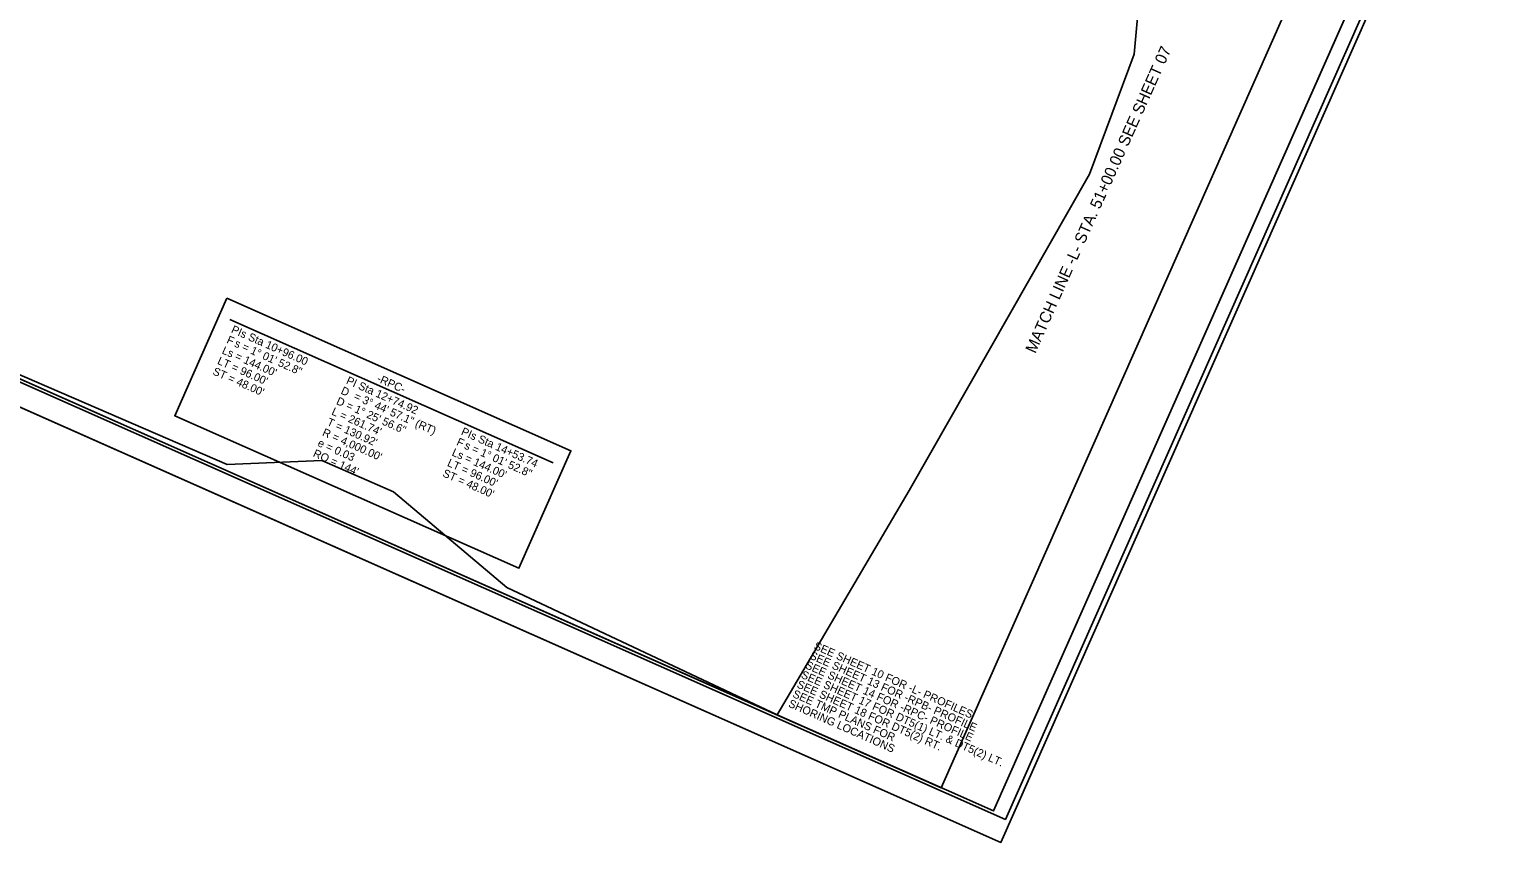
# Model space of a CAD drawing. Extents: x 1638962 to 2864602, y 841929 to 973236.
# Drawn here: x 1639652 to 1640945, y 841929 to 842639 of the extents above; entities that cross this region are included whole.
import ezdxf

# ---------------------------------------------------------------- set-up
doc = ezdxf.new("R2010")
doc.units = 0
for name, color, linetype in [('DEV STATIONARY SIGN DUAL MOUNT CELL', 7, 'Continuous'), ('Exist DTM Spot Elevation Cogo Number', 7, 'Continuous'), ('Exist Mkg Solid White Stop Bar', 7, 'Continuous'), ('Prop EOT', 7, 'Continuous'), ('Prop Mkg 3ft Min Skp 9ft White', 7, 'Continuous'), ('Prop Mkg Solid White Edge Line', 7, 'Continuous'), ('Prop Paved Shoulder', 7, 'Continuous'), ('Prop Roadway Bridge', 7, 'Continuous'), ('TCP Linework', 7, 'Continuous')]:
    doc.layers.add(name, color=color, linetype=linetype)

msp = doc.modelspace()

# ---------------------------------------------------------------- linework, layer by layer
at = {"layer": 'DEV STATIONARY SIGN DUAL MOUNT CELL'}
for points in [[(1640920.4, 842915.9), (1639549.1, 843524), (1639123.5, 842564.1), (1640494.7, 841956.1)], [(1639123.5, 842564.1), (1639549.1, 843523.9), (1640737.5, 842997), (1640676.7, 842859.8), (1640859.5, 842778.8), (1640494.7, 841956.1)]]:
    msp.add_lwpolyline(points, close=True, dxfattribs=at)
at = {"layer": 'Exist DTM Spot Elevation Cogo Number'}
msp.add_line((1639826.8, 842385.7), (1640109.4, 842260.4), dxfattribs=at)
msp.add_line((1639826.8, 842385.7), (1640109.4, 842260.4), dxfattribs=at)
msp.add_lwpolyline([(1639824.1, 842404.3), (1640125, 842270.9), (1640079.5, 842168.2), (1639778.6, 842301.6)], close=True, dxfattribs=at)
msp.add_lwpolyline([(1639824.1, 842404.3), (1640125, 842270.9), (1640079.5, 842168.2), (1639778.6, 842301.6)], close=True, dxfattribs=at)
at = {"layer": 'Prop EOT'}
msp.add_lwpolyline([(1639169.2, 842543.8), (1640449, 841976.3), (1640788.9, 842742.9), (1640615.9, 842819.6), (1640701.6, 843012.9), (1639594.8, 843503.7)], close=True, dxfattribs=at)
msp.add_lwpolyline([(1640629.1, 842742.4), (1640617.7, 842617.6), (1640578.7, 842512.8), (1640420.8, 842236.2), (1640305.4, 842040), (1640068.9, 842151.5), (1639969.8, 842235), (1639907.3, 842262.5), (1639824.3, 842259), (1639335.5, 842470.1)], dxfattribs=at)
at = {"layer": 'Prop Mkg 3ft Min Skp 9ft White'}
msp.add_line((1638962.2, 842611), (1640501.1, 841928.6), dxfattribs=at)
at = {"layer": 'Prop Mkg Solid White Edge Line'}
msp.add_line((1640578.7, 842512.8), (1640617.7, 842617.5), dxfattribs=at)
for points in [[(1640484.6, 842999.7), (1640629.1, 842742.4), (1640617.7, 842617.5)], [(1640578.7, 842512.8), (1640578.7, 842512.8), (1640420.8, 842236.2)]]:
    msp.add_lwpolyline(points, dxfattribs=at)
at = {"layer": 'Prop Paved Shoulder'}
msp.add_lwpolyline([(1638982.1, 842624), (1640505.1, 841948.7), (1640932.8, 842913.1), (1639409.8, 843588.4)], close=True, dxfattribs=at)
at = {"layer": 'Prop Roadway Bridge'}
msp.add_lwpolyline([(1638962.2, 842611), (1640501.1, 841928.6), (1640945, 842929.6), (1639406, 843612)], close=True, dxfattribs=at)
msp.add_lwpolyline([(1638962.2, 842611), (1640501.1, 841928.6), (1640945, 842929.6), (1639406, 843612)], close=True, dxfattribs=at)

# ---------------------------------------------------------------- texts
at = {"layer": 'Exist DTM Spot Elevation Cogo Number'}
for s, p in [('PIs Sta 10+96.00', (1639827.3, 842374.5)), ("Ls = 144.00'", (1639819.2, 842356.2)), ('F', (1639823.3, 842365.4)), ('s = 1%%d 01\' 52.8"', (1639830.1, 842362.3)), ("LT = 96.00'", (1639815.2, 842347.1)), ("ST = 48.00'", (1639811.1, 842337.9)), ('PI Sta 12+74.92', (1639927.9, 842329.9)), ('-RPC-', (1639954.7, 842331.7)), ('-RPC-', (1639954.7, 842331.7)), ('D', (1639923.2, 842321)), ("L = 261.74'", (1639915.1, 842302.8)), ('D = 1%%d 25\' 56.6"', (1639919.2, 842311.9)), ('= 3%%d 44\' 57.1" (RT)', (1639934.6, 842316.1)), ("T = 130.92'", (1639911, 842293.6)), ("R = 4,000.00'", (1639907, 842284.5)), ('F', (1640024.4, 842276.2)), ('PIs Sta 14+53.74', (1640028.4, 842285.3)), ("RO = 144'", (1639898.9, 842266.2)), ("RO = 144'", (1639898.9, 842266.2)), ('e = 0.03', (1639902.9, 842275.3)), ('e = 0.03', (1639902.9, 842275.3)), ("Ls = 144.00'", (1640020.3, 842267)), ('s = 1%%d 01\' 52.8"', (1640031.2, 842273.1)), ("LT = 96.00'", (1640016.3, 842257.9)), ("ST = 48.00'", (1640012.2, 842248.8))]:
    msp.add_text(s, height=7, rotation=336.0871, dxfattribs=at).set_placement(p)
at = {"layer": 'Exist Mkg Solid White Stop Bar'}
msp.add_text('MATCH LINE -L- STA. 51+00.00 SEE SHEET 07', height=10, rotation=65.8821, dxfattribs=at).set_placement((1640531.2, 842355.4))
at = {"layer": 'TCP Linework'}
for s, p in [('SEE SHEET 10 FOR -L- PROFILES', (1640336.9, 842097.9)), ('SEE SHEET 13 FOR -RPB- PROFILE', (1640333.2, 842089.5)), ('SEE SHEET 17 FOR DT5(1) LT. & DT5(2) LT.', (1640325.7, 842072.7)), ('SEE SHEET 14 FOR -RPC- PROFILE', (1640329.4, 842081.1)), ('SEE SHEET 18 FOR DT5(2) RT.', (1640322, 842064.3)), ('SHORING LOCATIONS', (1640314.6, 842047.5)), ('SEE TMP PLANS FOR', (1640318.3, 842055.9))]:
    msp.add_text(s, height=7, rotation=336.0871, dxfattribs=at).set_placement(p)

doc.saveas('drawing.dxf')
